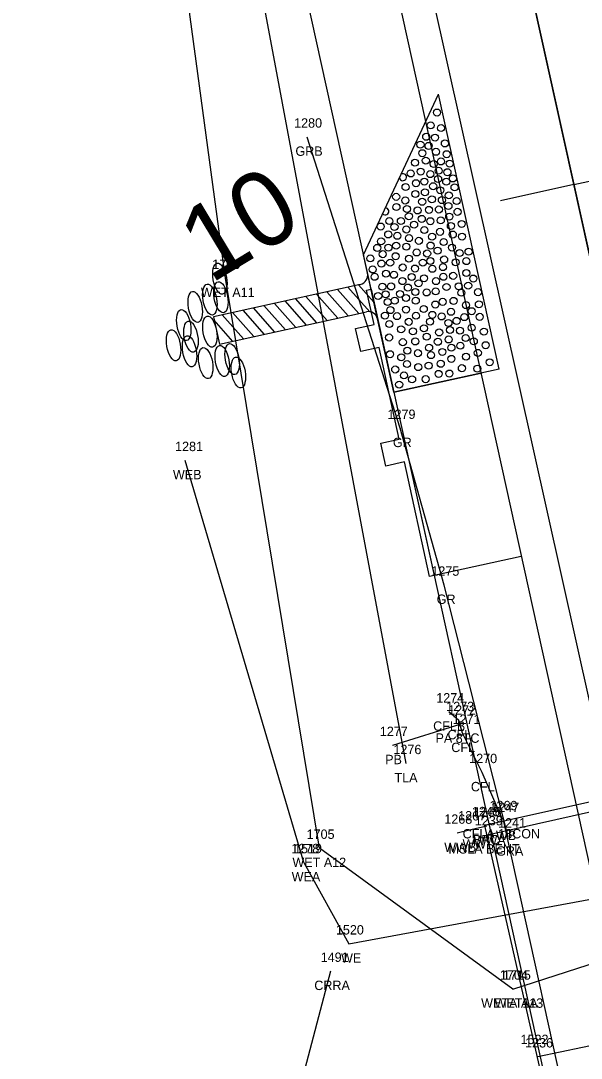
# Model space of a CAD drawing. Extents: x 2521558 to 2524785, y 882711 to 887632.
# Drawn here: x 2523708.7 to 2523768.4, y 885126.7 to 885237.2 of the extents above; entities that cross this region are included whole.
import ezdxf

# ---------------------------------------------------------------- set-up
doc = ezdxf.new("R2010")
doc.units = 0
for name, color, linetype in [('RD_EV_JurisArea', 7, 'Continuous'), ('RD_EX_BldgApp', 7, 'Continuous'), ('RD_EX_BldgApp_txCode', 7, 'Continuous'), ('RD_EX_Bridge', 7, 'Continuous'), ('RD_EX_Bridge_txCode', 7, 'Continuous'), ('RD_EX_Conc', 7, 'Continuous'), ('RD_EX_Conc_txCode', 7, 'Continuous'), ('RD_EX_DR_Pipe', 7, 'Continuous'), ('RD_EX_DR_Pipe_txCode', 7, 'Continuous'), ('RD_EX_GuardRail', 7, 'Continuous'), ('RD_EX_GuardRail_txCode', 7, 'Continuous'), ('RD_EX_H2O', 7, 'Continuous'), ('RD_EX_H2O_txCode', 7, 'Continuous'), ('RD_EX_H2O_WetLd_txCode', 7, 'Continuous'), ('RD_EX_Misc', 7, 'Continuous'), ('RD_EX_Misc_txCode', 7, 'Continuous'), ('RD_EX_Road', 7, 'Continuous'), ('RD_EX_VEG', 7, 'Continuous'), ('RD_EX_VEG_txCode', 7, 'Continuous'), ('RD_HC_Cl', 7, 'Continuous'), ('RD_HC_Data_Tic', 7, 'Continuous'), ('RD_HC_TX_Sta50', 7, 'Continuous'), ('RD_PD_Bridge', 7, 'Continuous'), ('RD_PD_Final_TrvlWay', 7, 'Continuous'), ('RD_PD_GR', 7, 'Continuous'), ('RD_PD_PaveShd', 7, 'Continuous'), ('RD_PD_SuperShp1', 7, 'Continuous'), ('RD_SMD_Locator', 7, 'Continuous')]:
    doc.layers.add(name, color=color, linetype=linetype)

# ---------------------------------------------------------------- blocks, each defined once
blk = doc.blocks.new('TBC1')
at = {"layer": 'RD_PD_GR'}
blk.add_lwpolyline([(12.5, 2.5), (15, 2.5), (15, 0.49), (25, 0.49), (25, 2.5), (27.5, 2.5), (27.5, 0.49), (31.25, 0.49), (31.25, 0), (0, 0), (0, 0.49), (12.5, 0.49)], close=True, dxfattribs=at)

msp = doc.modelspace()

# ---------------------------------------------------------------- linework, layer by layer
at = {"layer": 'RD_EV_JurisArea'}
for points in [[(2523761.17, 885134.03), (2523740.58, 885149.03), (2523730.55, 885209.77), (2523710.6, 885357.47), (2523698.09, 885411.19), (2523674.93, 885498.62), (2523657.6, 885564.24), (2523640.82, 885610.87), (2523583.66, 885726.91), (2523539.21, 885693.17), (2523494.42, 885646.98)], [(2523761.17, 885134.03), (2523808.21, 885149.21), (2523821.91, 885178.64), (2523802.85, 885236.55), (2523777.81, 885305.56), (2523748.2, 885444.32), (2523730.68, 885516.88), (2523708.64, 885617.3), (2523698.71, 885662.02), (2523727.83, 885665.82), (2523757.3, 885671.75)]]:
    msp.add_lwpolyline(points, dxfattribs=at)
at = {"layer": 'RD_EX_BldgApp'}
msp.add_lwpolyline([(2523776.68, 885077.92), (2523768.27, 885115.31), (2523760.2, 885151.9)], dxfattribs=at)
at = {"layer": 'RD_EX_Bridge'}
for points in [[(2523774.91, 885077.6), (2523821.2, 885087.83), (2523805.06, 885161.89), (2523758.15, 885151.44), (2523774.91, 885077.6)], [(2523758.38, 885151.39), (2523756.7, 885150.99), (2523755.23, 885150.64)]]:
    msp.add_lwpolyline(points, dxfattribs=at)
at = {"layer": 'RD_EX_Conc'}
msp.add_lwpolyline([(2523760.04, 885152.08), (2523757.9, 885157.1), (2523755.8, 885161.28), (2523755.4, 885162.64), (2523754.34, 885163.56)], dxfattribs=at)
at = {"layer": 'RD_EX_DR_Pipe'}
msp.add_line((2523755.61, 885162.27), (2523748.33, 885159.99), dxfattribs=at)
at = {"layer": 'RD_EX_GuardRail'}
for p, q in [((2523749.16, 885193.78), (2523739.25, 885224.82)), ((2523753.83, 885177.07), (2523749.16, 885193.78)), ((2523760.65, 885150.24), (2523753.83, 885177.07))]:
    msp.add_line(p, q, dxfattribs=at)
at = {"layer": 'RD_EX_H2O'}
msp.add_line((2523738.91, 885147.5), (2523726.24, 885190.35), dxfattribs=at)
for points in [[(2523738.91, 885147.5), (2523743.69, 885138.84), (2523816.36, 885152.29), (2523822.43, 885163.3), (2523826.93, 885206.61)], [(2523741.75, 885135.92), (2523732.18, 885099.57), (2523664.9, 885060.26), (2523614.86, 885022.02), (2523558.95, 884972.63), (2523560.62, 884942.42), (2523490.01, 884911.76)]]:
    msp.add_lwpolyline(points, dxfattribs=at)
at = {"layer": 'RD_EX_Misc'}
for p, q in [((2523758.45, 885150.47), (2523805.66, 885161.06)), ((2523810.71, 885136.57), (2523763.83, 885126.8))]:
    msp.add_line(p, q, dxfattribs=at)
at = {"layer": 'RD_EX_Road'}
msp.add_line((2523771.58, 885154.56), (2523750.32, 885250.18), dxfattribs=at)
at = {"layer": 'RD_EX_VEG'}
msp.add_lwpolyline([(2523749.81, 885158.06), (2523732.86, 885248.57), (2523691.62, 885438.95), (2523639.52, 885601.04)], dxfattribs=at)
at = {"layer": 'RD_HC_Cl'}
msp.add_line((2523641.17, 885794.2), (2524197.76, 883266.56), dxfattribs=at)
at = {"layer": 'RD_HC_Data_Tic'}
for q in [(2523775.47, 885221.48), (2523759.85, 885218.04)]:
    msp.add_line((2523767.66, 885219.76), q, dxfattribs=at)
at = {"layer": 'RD_PD_Bridge'}
msp.add_line((2523748.47, 885197.62), (2523757.75, 885199.66), dxfattribs=at)
for points in [[(2523748.47, 885197.62), (2523785.03, 885031.6)], [(2523762.05, 885180.13), (2523752.77, 885178.09)]]:
    msp.add_lwpolyline(points, dxfattribs=at)
at = {"layer": 'RD_PD_Final_TrvlWay'}
msp.add_line((2523697, 885475.55), (2524012.05, 884044.83), dxfattribs=at)
at = {"layer": 'RD_PD_GR'}
msp.add_line((2523746.05, 885208.61), (2523684.39, 885488.64), dxfattribs=at)
at = {"layer": 'RD_PD_PaveShd'}
for p, q in [((2523745.25, 885212.27), (2523753.25, 885229.39)), ((2523759.7, 885200.09), (2523753.25, 885229.39)), ((2523745.89, 885209.34), (2523745.25, 885212.27)), ((2523744.91, 885209.12), (2523729.27, 885205.67)), ((2523743.63, 885205.77), (2523741.35, 885208.34)), ((2523743.63, 885205.77), (2523741.35, 885208.34)), ((2523744.75, 885206.01), (2523742.47, 885208.58)), ((2523744.75, 885206.01), (2523742.47, 885208.58)), ((2523745.91, 885206.21), (2523743.59, 885208.83)), ((2523746.36, 885207.21), (2523744.71, 885209.08)), ((2523746.54, 885206.41), (2523745.89, 885209.34)), ((2523739.16, 885204.78), (2523736.89, 885207.35)), ((2523739.16, 885204.78), (2523736.89, 885207.35)), ((2523740.28, 885205.03), (2523738, 885207.6)), ((2523740.28, 885205.03), (2523738, 885207.6)), ((2523741.39, 885205.27), (2523739.12, 885207.84)), ((2523741.39, 885205.27), (2523739.12, 885207.84)), ((2523742.51, 885205.52), (2523740.24, 885208.09)), ((2523742.51, 885205.52), (2523740.24, 885208.09)), ((2523746.32, 885207.38), (2523746.32, 885207.38)), ((2523729.91, 885202.74), (2523745.56, 885206.19)), ((2523733.58, 885203.55), (2523731.3, 885206.12)), ((2523733.58, 885203.55), (2523731.3, 885206.12)), ((2523734.69, 885203.79), (2523732.42, 885206.36)), ((2523734.69, 885203.79), (2523732.42, 885206.36)), ((2523735.81, 885204.04), (2523733.54, 885206.61)), ((2523735.81, 885204.04), (2523733.54, 885206.61)), ((2523736.93, 885204.29), (2523734.65, 885206.86)), ((2523736.93, 885204.29), (2523734.65, 885206.86)), ((2523738.04, 885204.53), (2523735.77, 885207.1)), ((2523738.04, 885204.53), (2523735.77, 885207.1)), ((2523746.54, 885206.41), (2523748.47, 885197.62)), ((2523748.47, 885197.62), (2523746.54, 885206.41)), ((2523729.27, 885205.67), (2523729.91, 885202.74)), ((2523729.27, 885205.67), (2523729.91, 885202.74)), ((2523731.34, 885203.05), (2523729.35, 885205.31)), ((2523731.34, 885203.05), (2523729.35, 885205.31)), ((2523732.46, 885203.3), (2523730.18, 885205.87)), ((2523732.46, 885203.3), (2523730.18, 885205.87)), ((2523759.7, 885200.09), (2523748.47, 885197.62))]:
    msp.add_line(p, q, dxfattribs=at)
for centre in [(2523753.08, 885227.43), (2523753.08, 885227.43), (2523752.41, 885226.06), (2523752.41, 885226.06), (2523753.51, 885225.78), (2523753.51, 885225.78), (2523751.93, 885224.85), (2523751.93, 885224.85), (2523752.87, 885224.76), (2523752.87, 885224.76), (2523751.32, 885224.01), (2523752.18, 885223.88), (2523752.18, 885223.88), (2523753.92, 885224.14), (2523753.92, 885224.14), (2523751.52, 885223.1), (2523752.97, 885223.25), (2523752.97, 885223.25), (2523754.11, 885222.99), (2523754.11, 885222.99), (2523750.73, 885222.09), (2523750.73, 885222.09), (2523751.89, 885222.31), (2523751.89, 885222.31), (2523752.73, 885221.95), (2523752.73, 885221.95), (2523753.25, 885221.23), (2523753.25, 885221.23), (2523753.5, 885222.22), (2523753.5, 885222.22), (2523754.42, 885221.99), (2523754.42, 885221.99), (2523750.28, 885220.94), (2523750.28, 885220.94), (2523751.33, 885221.14), (2523751.33, 885221.14), (2523752.36, 885220.87), (2523752.36, 885220.87), (2523753.2, 885220.35), (2523753.2, 885220.35), (2523754.19, 885221.07), (2523754.19, 885221.07), (2523754.77, 885220.41), (2523754.77, 885220.41), (2523749.73, 885219.49), (2523749.73, 885219.49), (2523750.84, 885219.9), (2523750.84, 885219.9), (2523751.73, 885220.07), (2523751.73, 885220.07), (2523752.67, 885219.58), (2523752.67, 885219.58), (2523753.43, 885219.15), (2523753.43, 885219.15), (2523754.06, 885220.06), (2523754.06, 885220.06), (2523754.95, 885219.46), (2523754.95, 885219.46), (2523748.73, 885218.45), (2523749.7, 885218.06), (2523749.7, 885218.06), (2523750.78, 885218.75), (2523750.78, 885218.75), (2523751.5, 885217.92), (2523751.5, 885217.92), (2523751.79, 885218.93), (2523751.79, 885218.93), (2523752.53, 885218.18), (2523752.53, 885218.18), (2523753.6, 885218.1), (2523753.6, 885218.1), (2523754.34, 885218.6), (2523754.34, 885218.6), (2523755.18, 885218), (2523755.18, 885218), (2523748.76, 885217.36), (2523748.76, 885217.36), (2523749.87, 885217.15), (2523749.87, 885217.15), (2523751.01, 885217), (2523751.01, 885217), (2523752.22, 885217.06), (2523752.22, 885217.06), (2523753.28, 885217.1), (2523753.28, 885217.1), (2523754.3, 885217.47), (2523754.3, 885217.47), (2523755.27, 885216.85), (2523755.27, 885216.85), (2523748, 885215.87), (2523748, 885215.87), (2523749.23, 885215.87), (2523749.23, 885215.87), (2523750.08, 885216.38), (2523750.08, 885216.38), (2523751.46, 885216.1), (2523751.46, 885216.1), (2523752.37, 885215.85), (2523752.37, 885215.85), (2523753.48, 885215.94), (2523753.48, 885215.94), (2523754.38, 885216.34), (2523754.38, 885216.34), (2523747.08, 885215.28), (2523748.55, 885215.24), (2523748.55, 885215.24), (2523749.82, 885214.97), (2523749.82, 885214.97), (2523750.64, 885215.48), (2523750.64, 885215.48), (2523751.73, 885214.91), (2523751.73, 885214.91), (2523753.4, 885214.72), (2523753.4, 885214.72), (2523754.56, 885215.35), (2523754.56, 885215.35), (2523755.7, 885215.56), (2523755.7, 885215.56), (2523747.13, 885213.7), (2523747.13, 885213.7), (2523747.88, 885214.44), (2523747.88, 885214.44), (2523748.85, 885214.3), (2523748.85, 885214.3), (2523750.1, 885214.05), (2523750.1, 885214.05), (2523751.15, 885213.76), (2523751.15, 885213.76), (2523752.56, 885214.2), (2523752.56, 885214.2), (2523753.78, 885213.63), (2523753.78, 885213.63), (2523754.76, 885214.43), (2523754.76, 885214.43), (2523755.75, 885214.21), (2523755.75, 885214.21), (2523746.71, 885213.01), (2523747.91, 885213.04), (2523747.91, 885213.04), (2523748.73, 885213.24), (2523748.73, 885213.24), (2523749.82, 885213.14), (2523749.82, 885213.14), (2523750.91, 885212.52), (2523750.91, 885212.52), (2523752.03, 885212.41), (2523752.03, 885212.41), (2523752.39, 885213.26), (2523752.39, 885213.26), (2523753.14, 885212.71), (2523753.14, 885212.71), (2523754.68, 885213.04), (2523754.68, 885213.04), (2523755.48, 885212.46), (2523755.48, 885212.46), (2523756.44, 885212.6), (2523756.44, 885212.6), (2523745.98, 885211.89), (2523745.98, 885211.89), (2523747.16, 885211.34), (2523747.16, 885211.34), (2523747.3, 885212.34), (2523747.3, 885212.34), (2523747.3, 885212.34), (2523748.09, 885211.43), (2523748.09, 885211.43), (2523748.67, 885212.12), (2523748.67, 885212.12), (2523750.09, 885211.86), (2523750.09, 885211.86), (2523751.57, 885211.44), (2523751.57, 885211.44), (2523752.37, 885211.61), (2523752.37, 885211.61), (2523753.84, 885211.77), (2523753.84, 885211.77), (2523755.06, 885211.47), (2523755.06, 885211.47), (2523756.21, 885211.6), (2523756.21, 885211.6), (2523746.23, 885210.71), (2523746.23, 885210.71), (2523747.64, 885210.26), (2523747.64, 885210.26), (2523749.43, 885210.92), (2523749.43, 885210.92), (2523750.73, 885210.81), (2523750.73, 885210.81), (2523752.58, 885210.78), (2523752.58, 885210.78), (2523753.71, 885210.96), (2523753.71, 885210.96), (2523756.2, 885210.33), (2523756.2, 885210.33), (2523746.43, 885209.93), (2523746.43, 885209.93), (2523748.49, 885210.14), (2523748.49, 885210.14), (2523749.4, 885209.47), (2523749.4, 885209.47), (2523750.38, 885209.91), (2523750.38, 885209.91), (2523751.11, 885209.24), (2523751.11, 885209.24), (2523751.7, 885209.77), (2523751.7, 885209.77), (2523752.97, 885209.47), (2523752.97, 885209.47), (2523753.76, 885209.93), (2523753.76, 885209.93), (2523754.8, 885210.03), (2523754.8, 885210.03), (2523756.94, 885209.74), (2523747.27, 885208.87), (2523747.27, 885208.87), (2523747.62, 885208.06), (2523747.62, 885208.06), (2523748.19, 885208.9), (2523748.19, 885208.9), (2523749.13, 885208.1), (2523749.13, 885208.1), (2523749.98, 885208.78), (2523749.98, 885208.78), (2523750.77, 885208.31), (2523750.77, 885208.31), (2523751.97, 885208.26), (2523751.97, 885208.26), (2523752.93, 885208.37), (2523752.93, 885208.37), (2523754.09, 885208.84), (2523754.09, 885208.84), (2523755.38, 885208.92), (2523755.38, 885208.92), (2523755.68, 885208.23), (2523755.68, 885208.23), (2523756.4, 885208.98), (2523756.4, 885208.98), (2523757.45, 885208.29), (2523757.45, 885208.29), (2523746.81, 885207.89), (2523746.81, 885207.89), (2523747.82, 885207.24), (2523747.82, 885207.24), (2523748.58, 885207.38), (2523748.58, 885207.38), (2523749.78, 885207.67), (2523749.78, 885207.67), (2523750.82, 885207.38), (2523750.82, 885207.38), (2523752.9, 885206.97), (2523752.9, 885206.97), (2523753.68, 885207.26), (2523753.68, 885207.26), (2523754.84, 885207.36), (2523754.84, 885207.36), (2523756.16, 885206.91), (2523756.16, 885206.91), (2523757.54, 885207), (2523757.54, 885207), (2523747.53, 885205.79), (2523747.53, 885205.79), (2523748.12, 885206.38), (2523749.78, 885206.43), (2523749.78, 885206.43), (2523750.84, 885205.78), (2523750.84, 885205.78), (2523751.67, 885206.49), (2523751.67, 885206.49), (2523752.58, 885205.87), (2523752.58, 885205.87), (2523754.57, 885206.2), (2523754.57, 885206.2), (2523756.77, 885206.26), (2523756.77, 885206.26), (2523748.01, 885204.89), (2523748.01, 885204.89), (2523748.82, 885205.74), (2523748.82, 885205.74), (2523750.07, 885205.13), (2523750.07, 885205.13), (2523752.34, 885205.15), (2523752.34, 885205.15), (2523753.57, 885205.7), (2523753.57, 885205.7), (2523754.3, 885205.01), (2523754.3, 885205.01), (2523755.16, 885205.23), (2523755.16, 885205.23), (2523755.99, 885205.63), (2523755.99, 885205.63), (2523757.63, 885205.66), (2523757.63, 885205.66), (2523749.26, 885204.33), (2523749.26, 885204.33), (2523750.51, 885204.12), (2523750.51, 885204.12), (2523751.68, 885204.44), (2523751.68, 885204.44), (2523751.99, 885203.55), (2523751.99, 885203.55), (2523753.31, 885204), (2523753.31, 885204), (2523754.46, 885204.26), (2523755.52, 885204.19), (2523755.52, 885204.19), (2523756.78, 885204.5), (2523756.78, 885204.5), (2523758.07, 885204.09), (2523758.07, 885204.09), (2523747.98, 885203.46), (2523747.98, 885203.46), (2523749.44, 885202.96), (2523749.44, 885202.96), (2523750.76, 885203.04), (2523750.76, 885203.04), (2523753.17, 885203), (2523753.17, 885203), (2523754.32, 885203.25), (2523754.32, 885203.25), (2523755.57, 885202.58), (2523755.57, 885202.58), (2523756.14, 885203.4), (2523756.14, 885203.4), (2523757, 885203.06), (2523757, 885203.06), (2523758.26, 885202.64), (2523758.26, 885202.64), (2523748.08, 885201.68), (2523748.08, 885201.68), (2523749.27, 885201.35), (2523749.27, 885201.35), (2523749.92, 885202.06), (2523749.92, 885202.06), (2523751.05, 885201.79), (2523751.05, 885201.79), (2523752.24, 885202.37), (2523752.24, 885202.37), (2523752.44, 885201.58), (2523752.44, 885201.58), (2523753.64, 885201.92), (2523753.64, 885201.92), (2523754.62, 885202.37), (2523754.62, 885202.37), (2523756.17, 885201.42), (2523756.17, 885201.42), (2523757.43, 885201.82), (2523757.43, 885201.82), (2523749.89, 885200.63), (2523749.89, 885200.63), (2523751.08, 885200.3), (2523751.08, 885200.3), (2523752.18, 885200.46), (2523752.18, 885200.46), (2523753.48, 885200.66), (2523753.48, 885200.66), (2523754.61, 885201.18), (2523754.61, 885201.18), (2523758.69, 885200.82), (2523758.69, 885200.82), (2523748.63, 885200.05), (2523748.63, 885200.05), (2523749.56, 885199.42), (2523753.25, 885199.58), (2523753.25, 885199.58), (2523754.4, 885199.62), (2523754.4, 885199.62), (2523755.73, 885200.19), (2523755.73, 885200.19), (2523757.38, 885200.14), (2523757.38, 885200.14), (2523749.05, 885198.44), (2523749.05, 885198.44), (2523750.43, 885199), (2523750.43, 885199), (2523750.43, 885199), (2523751.87, 885199.02), (2523751.87, 885199.02)]:
    msp.add_circle(centre, 0.375, dxfattribs=at)
for centre, radius, start, end in [((2523749.45, 885220.54), 0.375, 191.7998, 118.0848), ((2523747.57, 885216.91), 0.375, 222.987, 86.8976), ((2523744.7, 885210.1), 1, 282.4481, 12.4185), ((2523745.77, 885205.22), 1, 12.4185, 102.4481)]:
    msp.add_arc(centre, radius, start, end, dxfattribs=at)
for centre in [(2523729.95, 885209.73), (2523730.06, 885207.75), (2523727.32, 885206.72), (2523727.32, 885206.72), (2523728.88, 885207.5), (2523728.88, 885207.5), (2523726.1, 885204.78), (2523726.1, 885204.78), (2523726.87, 885203.55), (2523726.87, 885203.55), (2523728.89, 885204.08), (2523728.89, 885204.08), (2523725.02, 885202.63), (2523725.02, 885202.63), (2523726.72, 885201.99), (2523726.72, 885201.99), (2523731.26, 885201.16), (2523731.26, 885201.16), (2523728.44, 885200.73), (2523728.44, 885200.73), (2523730.2, 885200.96), (2523730.2, 885200.96), (2523731.92, 885199.73), (2523731.92, 885199.73)]:
    msp.add_ellipse(centre, major_axis=(-0.29, 1.65), ratio=0.429445, dxfattribs=at)
at = {"layer": 'RD_PD_SuperShp1'}
for p, q in [((2524025.72, 884047.84), (2523710.67, 885478.56)), ((2523710.67, 885478.56), (2524025.72, 884047.84)), ((2523697, 885475.55), (2524012.05, 884044.83))]:
    msp.add_line(p, q, dxfattribs=at)
at = {"layer": 'RD_SMD_Locator'}
for centre in [(2523739.25, 885224.82), (2523730.55, 885209.77), (2523749.16, 885193.78), (2523726.24, 885190.35), (2523753.83, 885177.07), (2523754.34, 885163.56), (2523755.4, 885162.64), (2523755.61, 885162.27), (2523755.8, 885161.28), (2523748.33, 885159.99), (2523749.81, 885158.06), (2523757.9, 885157.1), (2523760.04, 885152.08), (2523756.7, 885150.99), (2523758.15, 885151.44), (2523758.38, 885151.39), (2523760.2, 885151.9), (2523755.23, 885150.64), (2523758.45, 885150.47), (2523760.65, 885150.24), (2523740.58, 885149.03), (2523738.91, 885147.5), (2523738.91, 885147.5), (2523743.69, 885138.84), (2523741.75, 885135.92), (2523761.17, 885134.03), (2523761.17, 885134.03), (2523763.32, 885127.16), (2523763.83, 885126.8)]:
    msp.add_circle(centre, 0.001, dxfattribs=at)

# ---------------------------------------------------------------- block references
at = {"layer": 'RD_PD_Bridge', "rotation": 102.41848259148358}
msp.add_blockref('TBC1', (2523752.77, 885178.09), dxfattribs=at)

# ---------------------------------------------------------------- texts
at = {"layer": 'RD_EX_BldgApp_txCode'}
for s, p in [('1247', (2523758.86, 885152.9)), ('WB', (2523759.36, 885149.9)), ('1522', (2523761.98, 885128.16))]:
    msp.add_text(s, height=1, dxfattribs=at).set_placement(p)
at = {"layer": 'RD_EX_Bridge_txCode'}
for s, p in [('1245', (2523756.8, 885152.44)), ('1266', (2523756.98, 885152.39)), ('1268', (2523753.86, 885151.64)), ('1267', (2523755.33, 885151.99)), ('WW', (2523755.8, 885148.99)), ('WWA', (2523756.98, 885149.39)), ('BRC', (2523756.89, 885149.44)), ('WWB', (2523753.85, 885148.64))]:
    msp.add_text(s, height=1, dxfattribs=at).set_placement(p)
at = {"layer": 'RD_EX_Conc_txCode'}
for s, p in [('1274', (2523753, 885164.56)), ('1273', (2523754.06, 885163.64)), ('1271', (2523754.74, 885162.28)), ('CFLB', (2523752.67, 885161.56)), ('CFL', (2523754.2, 885160.64)), ('CFL', (2523754.6, 885159.28)), ('1270', (2523756.51, 885158.1)), ('CFL', (2523756.69, 885155.1)), ('1269', (2523758.67, 885153.08)), ('CFLA 18CON', (2523755.81, 885150.08))]:
    msp.add_text(s, height=1, dxfattribs=at).set_placement(p)
at = {"layer": 'RD_EX_DR_Pipe_txCode'}
for s, p in [('1272', (2523754.27, 885163.27)), ('1277', (2523746.99, 885160.99)), ('PA 8TC', (2523752.92, 885160.27)), ('PB', (2523747.56, 885157.99))]:
    msp.add_text(s, height=1, dxfattribs=at).set_placement(p)
at = {"layer": 'RD_EX_GuardRail_txCode'}
for s, p in [('1280', (2523737.86, 885225.82)), ('GRB', (2523738, 885222.82)), ('1279', (2523747.81, 885194.78)), ('GR', (2523748.38, 885191.78)), ('1275', (2523752.48, 885178.07)), ('GR', (2523753.05, 885175.07)), ('1241', (2523759.59, 885151.24)), ('GRA', (2523759.38, 885148.24))]:
    msp.add_text(s, height=1, dxfattribs=at).set_placement(p)
at = {"layer": 'RD_EX_H2O_txCode'}
for s, p in [('1281', (2523725.18, 885191.35)), ('WEB', (2523724.95, 885188.35)), ('1278', (2523737.56, 885148.5)), ('1519', (2523737.85, 885148.5)), ('WEA', (2523737.6, 885145.5)), ('WEA', (2523737.6, 885145.5)), ('1520', (2523742.31, 885139.84)), ('1491', (2523740.69, 885136.92)), ('WE', (2523742.86, 885136.84)), ('CRRA', (2523740.01, 885133.92))]:
    msp.add_text(s, height=1, dxfattribs=at).set_placement(p)
at = {"layer": 'RD_EX_H2O_WetLd_txCode'}
for s, p in [('1706', (2523729.14, 885210.77)), ('WET A11', (2523727.93, 885207.77)), ('1705', (2523739.19, 885150.03)), ('WET A12', (2523737.68, 885147.03)), ('1704', (2523759.78, 885135.03)), ('1715', (2523760.1, 885135.03)), ('WETA A13', (2523757.78, 885132.03)), ('WET1A', (2523759.21, 885132.03))]:
    msp.add_text(s, height=1, dxfattribs=at).set_placement(p)
at = {"layer": 'RD_EX_Misc_txCode'}
for s, p in [('1239', (2523757.11, 885151.47)), ('MSLA BENT', (2523754.3, 885148.47)), ('1236', (2523762.46, 885127.8))]:
    msp.add_text(s, height=1, dxfattribs=at).set_placement(p)
at = {"layer": 'RD_EX_VEG_txCode'}
for s, p in [('1276', (2523748.44, 885159.06)), ('TLA', (2523748.55, 885156.06))]:
    msp.add_text(s, height=1, dxfattribs=at).set_placement(p)
at = {"layer": 'RD_HC_TX_Sta50'}
msp.add_text('10', height=8, rotation=31.1184, dxfattribs=at).set_placement((2523728.92, 885209.12))

doc.saveas('drawing.dxf')
